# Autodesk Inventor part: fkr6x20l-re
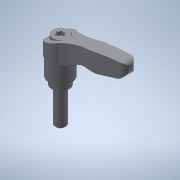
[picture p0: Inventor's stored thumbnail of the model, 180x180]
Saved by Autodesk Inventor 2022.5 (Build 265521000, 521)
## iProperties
Created: 2017-09
Part Number: fkr6x20l-re
Material: 一般
Document SubType Name: Modeling
Designer: imaocorp
Density: 1 g/cm^3
Appearance: 既定
Author: imaocorp
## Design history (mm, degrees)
node "fkr6x20l-re.x_t1"
node "fkr6x20l-re"
node "Base1"
